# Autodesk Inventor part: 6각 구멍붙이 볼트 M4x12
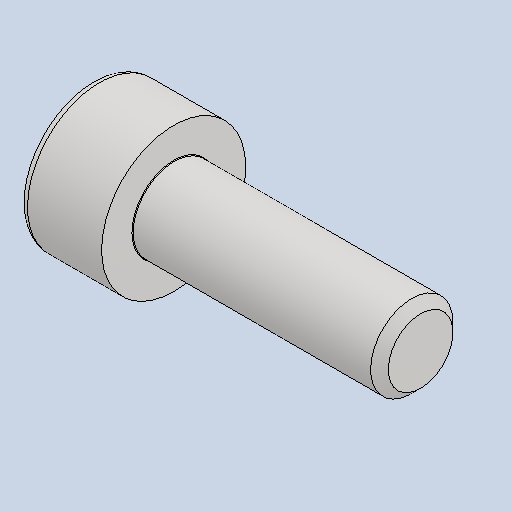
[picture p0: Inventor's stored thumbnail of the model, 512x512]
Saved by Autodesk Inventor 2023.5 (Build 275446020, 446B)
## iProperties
Created: 2026-08
Part Number: 6각 구멍붙이 볼트 M4x12
Material: 스테인리스강
Description: 6각 소켓 머리 캡 나사
Document SubType Name: Modeling
Designer: 1강의실14
Density: 8.08 g/cm^3
Appearance: 기본값
Author: jhkim
Sending System: Autodesk Inventor 2027
Preprocessor: ST-DEVELOPER v20.1
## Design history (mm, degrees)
node "6각 구멍붙이 볼트 M4x121"
node "솔리드1"
body "Solid1"
